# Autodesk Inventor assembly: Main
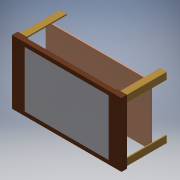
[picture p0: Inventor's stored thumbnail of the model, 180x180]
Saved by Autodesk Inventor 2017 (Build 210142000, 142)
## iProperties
Created: 2017-05
Part Number: Main
Document SubType Name: Assembly
Designer: Savy
Sending System: SIEMENS PLM Software NX 10.0
Preprocessor: ST-DEVELOPER v16
Title: Main_stp_stp.stp
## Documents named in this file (4)
- D:\Users\Savy\Documents\Infinity Table\Main.iam
- D:\Users\Savy\Documents\Infinity Table\Top.iam
- D:\Users\Savy\Documents\Infinity Table\Bottom.iam
- D:\Users\Savy\Documents\Infinity Table\Legs.iam
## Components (3 placed, 3 different names)
1. Top_1339 [sub-assembly]
2. Bottom_1340 [sub-assembly]
3. Legs_1341 [sub-assembly]
